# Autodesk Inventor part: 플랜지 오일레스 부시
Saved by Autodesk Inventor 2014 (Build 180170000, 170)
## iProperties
Created: 2026-03
Part Number: 플랜지 오일레스 부시
Material: 구리, 합금
Document SubType Name: Modeling
Designer: dg
Density: 7.58 g/cm^3
Appearance: 구리 - 새틴
Mass: 38.8385 g
Surface Area: 34.2906 cm^2
Volume: 5.12381 cm^3
Author: jhkim
Creation Date: 2025-06-27
Sending System: Autodesk Inventor 2026
Preprocessor: ST-DEVELOPER v20.1
Author: dg
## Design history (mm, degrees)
node "플랜지 오일레스 부시1"
node "솔리드1"
node "기준1"
